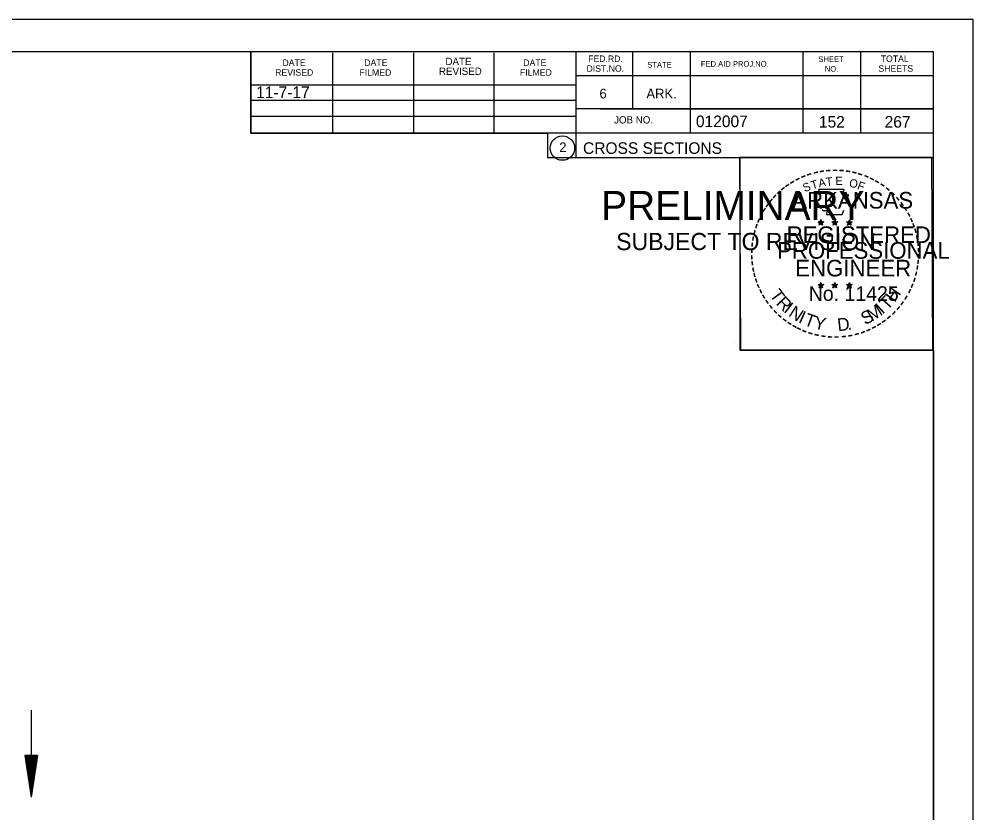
# Model space of a CAD drawing. Extents: x 1374311 to 1383814, y 384102 to 406278.
# Drawn here: x 1381676.6 to 1381791.6, y 385082.2 to 385178 of the extents above; entities that cross this region are included whole.
import ezdxf

# ---------------------------------------------------------------- set-up
doc = ezdxf.new("R2010")
doc.units = 0
for name, color, linetype in [('R_Border', 7, 'Continuous'), ('R_Border PE', 7, 'Continuous'), ('R_Border Prem', 7, 'Continuous'), ('R_Draft', 7, 'Continuous'), ('R_Fin Surface', 7, 'Continuous'), ('R_No Plot', 7, 'Continuous'), ('R_Water', 7, 'Continuous')]:
    doc.layers.add(name, color=color, linetype=linetype)

msp = doc.modelspace()

# ---------------------------------------------------------------- linework, layer by layer
at = {"layer": 'R_Border'}
for p, q in [((1381470.66, 385174.06), (1381786.84, 385174.06)), ((1381704.58, 385164.18), (1381704.58, 385174.06)), ((1381714.44, 385164.18), (1381714.44, 385173.86)), ((1381724.2, 385164.18), (1381724.2, 385173.86)), ((1381733.88, 385164.18), (1381733.88, 385173.86)), ((1381743.74, 385174.06), (1381743.74, 385161.26)), ((1381750.58, 385174.06), (1381750.58, 385167.12)), ((1381757.52, 385174.06), (1381757.52, 385164.18)), ((1381771.1, 385174.06), (1381771.1, 385164.18)), ((1381778.04, 385174.06), (1381778.04, 385164.18)), ((1381786.84, 384968.6), (1381786.84, 385174.06)), ((1381786.84, 385171.12), (1381743.74, 385171.12)), ((1381786.84, 385171.14), (1381786.84, 385171.14)), ((1381704.58, 385170.04), (1381743.74, 385170.04)), ((1381704.58, 385168.18), (1381743.74, 385168.18)), ((1381786.84, 385167.12), (1381743.74, 385167.12)), ((1381746.7, 385167.12), (1381786.84, 385167.12)), ((1381704.58, 385164.18), (1381704.58, 385166.24)), ((1381704.58, 385166.24), (1381743.74, 385166.24)), ((1381786.84, 385164.18), (1381704.58, 385164.18)), ((1381743.74, 385161.26), (1381786.84, 385161.26))]:
    msp.add_line(p, q, dxfattribs=at)
msp.add_circle((1381742.12, 385162.39), 1.47, dxfattribs=at)
at = {"layer": 'R_Border PE'}
for p, q in [((1381772.92, 385153.51), (1381773.27, 385153.4)), ((1381772.92, 385153.51), (1381773.18, 385153.47)), ((1381772.92, 385153.51), (1381773.16, 385153.39)), ((1381773.06, 385153.1), (1381773.27, 385153.4)), ((1381773.06, 385153.1), (1381773.18, 385153.35)), ((1381773.06, 385153.1), (1381773.27, 385153.32)), ((1381773.27, 385153.77), (1381773.23, 385153.51)), ((1381773.27, 385153.4), (1381773.27, 385153.77)), ((1381773.27, 385153.77), (1381773.32, 385153.52)), ((1381773.62, 385153.51), (1381773.27, 385153.4)), ((1381773.48, 385153.1), (1381773.27, 385153.4)), ((1381773.48, 385153.1), (1381773.27, 385153.32)), ((1381773.62, 385153.51), (1381773.33, 385153.46)), ((1381773.48, 385153.1), (1381773.35, 385153.39)), ((1381773.62, 385153.51), (1381773.41, 385153.41)), ((1381774.59, 385153.51), (1381774.94, 385153.4)), ((1381774.59, 385153.51), (1381774.85, 385153.47)), ((1381774.59, 385153.51), (1381774.83, 385153.39)), ((1381774.73, 385153.1), (1381774.94, 385153.4)), ((1381774.73, 385153.1), (1381774.85, 385153.35)), ((1381774.73, 385153.1), (1381774.94, 385153.32)), ((1381774.94, 385153.77), (1381774.9, 385153.51)), ((1381774.94, 385153.4), (1381774.94, 385153.77)), ((1381774.94, 385153.77), (1381774.99, 385153.52)), ((1381775.29, 385153.51), (1381774.94, 385153.4)), ((1381775.15, 385153.1), (1381774.94, 385153.4)), ((1381775.15, 385153.1), (1381774.94, 385153.32)), ((1381775.29, 385153.51), (1381775, 385153.46)), ((1381775.15, 385153.1), (1381775.02, 385153.39)), ((1381775.29, 385153.51), (1381775.08, 385153.41)), ((1381776.36, 385153.5), (1381776.71, 385153.39)), ((1381776.36, 385153.5), (1381776.61, 385153.45)), ((1381776.36, 385153.5), (1381776.59, 385153.38)), ((1381776.49, 385153.09), (1381776.71, 385153.39)), ((1381776.49, 385153.09), (1381776.62, 385153.34)), ((1381776.49, 385153.09), (1381776.7, 385153.31)), ((1381776.71, 385153.75), (1381776.66, 385153.5)), ((1381776.92, 385153.09), (1381776.7, 385153.31)), ((1381776.71, 385153.39), (1381776.71, 385153.75)), ((1381776.71, 385153.75), (1381776.75, 385153.5)), ((1381777.05, 385153.5), (1381776.71, 385153.39)), ((1381776.92, 385153.09), (1381776.71, 385153.39)), ((1381777.05, 385153.5), (1381776.77, 385153.45)), ((1381776.92, 385153.09), (1381776.78, 385153.38)), ((1381777.05, 385153.5), (1381776.85, 385153.4)), ((1381773.27, 385146.19), (1381773.23, 385145.94)), ((1381773.27, 385145.83), (1381773.27, 385146.19)), ((1381773.27, 385146.19), (1381773.32, 385145.94)), ((1381774.94, 385146.19), (1381774.9, 385145.94)), ((1381774.94, 385145.83), (1381774.94, 385146.19)), ((1381774.94, 385146.19), (1381774.99, 385145.94)), ((1381776.7, 385146.18), (1381776.66, 385145.93)), ((1381776.7, 385145.82), (1381776.7, 385146.18)), ((1381776.7, 385146.18), (1381776.75, 385145.93)), ((1381772.92, 385145.94), (1381773.27, 385145.83)), ((1381772.92, 385145.94), (1381773.17, 385145.89)), ((1381772.92, 385145.94), (1381773.16, 385145.82)), ((1381773.05, 385145.53), (1381773.27, 385145.83)), ((1381773.05, 385145.53), (1381773.18, 385145.77)), ((1381773.05, 385145.53), (1381773.27, 385145.75)), ((1381773.61, 385145.94), (1381773.27, 385145.83)), ((1381773.48, 385145.53), (1381773.27, 385145.83)), ((1381773.48, 385145.53), (1381773.27, 385145.74)), ((1381773.61, 385145.94), (1381773.33, 385145.89)), ((1381773.48, 385145.53), (1381773.34, 385145.82)), ((1381773.61, 385145.94), (1381773.41, 385145.84)), ((1381774.59, 385145.94), (1381774.94, 385145.83)), ((1381774.59, 385145.94), (1381774.84, 385145.89)), ((1381774.59, 385145.94), (1381774.82, 385145.82)), ((1381774.72, 385145.53), (1381774.94, 385145.83)), ((1381774.72, 385145.53), (1381774.85, 385145.77)), ((1381774.72, 385145.53), (1381774.93, 385145.75)), ((1381775.15, 385145.53), (1381774.93, 385145.74)), ((1381775.28, 385145.94), (1381774.94, 385145.83)), ((1381775.15, 385145.53), (1381774.94, 385145.83)), ((1381775.28, 385145.94), (1381775, 385145.89)), ((1381775.15, 385145.53), (1381775.01, 385145.82)), ((1381775.28, 385145.94), (1381775.08, 385145.84)), ((1381776.35, 385145.93), (1381776.7, 385145.82)), ((1381776.35, 385145.93), (1381776.61, 385145.88)), ((1381776.35, 385145.93), (1381776.59, 385145.81)), ((1381776.49, 385145.52), (1381776.7, 385145.82)), ((1381776.49, 385145.52), (1381776.61, 385145.76)), ((1381776.49, 385145.52), (1381776.7, 385145.74)), ((1381777.05, 385145.93), (1381776.7, 385145.82)), ((1381776.92, 385145.52), (1381776.7, 385145.82)), ((1381776.92, 385145.52), (1381776.7, 385145.73)), ((1381777.05, 385145.93), (1381776.76, 385145.88)), ((1381776.92, 385145.52), (1381776.78, 385145.81)), ((1381777.05, 385145.93), (1381776.85, 385145.83))]:
    msp.add_line(p, q, dxfattribs=at)
for points in [[(1381772.96, 385157.39), (1381773.23, 385156.56)], [(1381776.47, 385156.47), (1381776.62, 385156.75), (1381775.93, 385156.73), (1381776.08, 385157.39), (1381772.96, 385157.39)], [(1381773.46, 385154.97), (1381773.46, 385154.88), (1381774.02, 385154.86), (1381773.96, 385154.39), (1381775.83, 385154.39), (1381776.04, 385154.92)], [(1381773.27, 385153.77), (1381773.48, 385153.1), (1381772.92, 385153.51), (1381773.62, 385153.51), (1381773.06, 385153.1), (1381773.27, 385153.77)], [(1381774.94, 385153.77), (1381775.15, 385153.1), (1381774.59, 385153.51), (1381775.29, 385153.51), (1381774.73, 385153.1), (1381774.94, 385153.77)], [(1381776.71, 385153.75), (1381776.92, 385153.09), (1381776.36, 385153.5), (1381777.05, 385153.5), (1381776.49, 385153.09), (1381776.71, 385153.75)], [(1381773.27, 385146.19), (1381773.48, 385145.53), (1381772.92, 385145.94), (1381773.61, 385145.94), (1381773.05, 385145.53), (1381773.27, 385146.19)], [(1381774.94, 385146.19), (1381775.15, 385145.53), (1381774.59, 385145.94), (1381775.28, 385145.94), (1381774.72, 385145.53), (1381774.94, 385146.19)], [(1381776.7, 385146.18), (1381776.92, 385145.52), (1381776.35, 385145.93), (1381777.05, 385145.93), (1381776.49, 385145.52), (1381776.7, 385146.18)]]:
    msp.add_lwpolyline(points, dxfattribs=at)
for centre, radius in [((1381773.27, 385153.4), 0.172), ((1381773.27, 385153.4), 0.145), ((1381773.27, 385153.4), 0.116), ((1381773.27, 385153.4), 0.0991), ((1381773.27, 385153.4), 0.0747), ((1381773.27, 385153.4), 0.0495), ((1381773.27, 385153.4), 0.0296), ((1381774.94, 385153.4), 0.172), ((1381774.94, 385153.4), 0.145), ((1381774.94, 385153.4), 0.116), ((1381774.94, 385153.4), 0.0991), ((1381774.94, 385153.4), 0.0747), ((1381774.94, 385153.4), 0.0495), ((1381774.94, 385153.4), 0.0296), ((1381776.7, 385153.39), 0.172), ((1381776.7, 385153.39), 0.145), ((1381776.7, 385153.39), 0.116), ((1381776.7, 385153.39), 0.0991), ((1381776.7, 385153.39), 0.0747), ((1381776.7, 385153.39), 0.0495), ((1381776.7, 385153.39), 0.0296), ((1381773.27, 385145.83), 0.172), ((1381773.27, 385145.83), 0.145), ((1381773.27, 385145.83), 0.116), ((1381773.27, 385145.83), 0.0991), ((1381773.27, 385145.83), 0.0747), ((1381773.27, 385145.83), 0.0495), ((1381773.27, 385145.83), 0.0296), ((1381774.94, 385145.83), 0.172), ((1381774.94, 385145.83), 0.145), ((1381774.94, 385145.83), 0.116), ((1381774.94, 385145.83), 0.0991), ((1381774.94, 385145.83), 0.0747), ((1381774.94, 385145.83), 0.0495), ((1381774.94, 385145.83), 0.0296), ((1381776.7, 385145.82), 0.172), ((1381776.7, 385145.82), 0.145), ((1381776.7, 385145.82), 0.116), ((1381776.7, 385145.82), 0.0991), ((1381776.7, 385145.82), 0.0747), ((1381776.7, 385145.82), 0.0495), ((1381776.7, 385145.82), 0.0296)]:
    msp.add_circle(centre, radius, dxfattribs=at)
at = {"layer": 'R_Draft'}
for p, q in [((1381677.34, 385089.13), (1381678.09, 385084.13)), ((1381678.84, 385089.13), (1381677.34, 385089.13)), ((1381677.47, 385089.13), (1381678.09, 385084.96)), ((1381677.6, 385089.13), (1381678.09, 385085.82)), ((1381677.72, 385089.13), (1381678.09, 385086.65)), ((1381677.85, 385089.13), (1381678.09, 385087.5)), ((1381677.98, 385089.13), (1381678.09, 385088.34)), ((1381678.84, 385089.13), (1381678.09, 385084.13)), ((1381678.34, 385089.13), (1381678.09, 385087.5)), ((1381678.59, 385089.13), (1381678.09, 385085.82)), ((1381678.72, 385089.13), (1381678.09, 385084.96)), ((1381678.47, 385089.13), (1381678.09, 385086.65)), ((1381678.21, 385089.13), (1381678.09, 385088.34))]:
    msp.add_line(p, q, dxfattribs=at)
at = {"layer": 'R_No Plot'}
for p, q in [((1381458.26, 385177.95), (1381791.59, 385177.95)), ((1381762.87, 385138.8), (1381762.87, 385138.8))]:
    msp.add_line(p, q, dxfattribs=at)
for points in [[(1381458.25, 385177.95), (1381791.59, 385177.95), (1381791.59, 384964.61), (1381458.25, 384964.61)], [(1381704.58, 385174.06), (1381704.58, 385164.18), (1381740.31, 385164.18), (1381740.31, 385161.26), (1381763.51, 385161.26), (1381763.51, 385138.04), (1381786.84, 385138.04), (1381786.84, 384968.6), (1381470.66, 384968.6), (1381470.66, 385174.06)], [(1381763.51, 385161.29), (1381786.61, 385161.29), (1381786.72, 385138.04), (1381763.62, 385138.04)]]:
    msp.add_lwpolyline(points, close=True, dxfattribs=at)
at = {"layer": 'R_Water'}
msp.add_line((1381678.09, 385094.63), (1381678.09, 385084.13), dxfattribs=at)

# ---------------------------------------------------------------- texts
at = {"layer": 'R_Border'}
for s, height, p in [('DATE', 0.782, (1381708.38, 385172.3)), ('DATE', 0.782, (1381718.24, 385172.3)), ('DATE', 0.879, (1381728.02, 385172.4)), ('DATE', 0.782, (1381737.4, 385172.3)), ('FED.RD.', 0.782, (1381745.22, 385172.78)), ('STATE', 0.684, (1381752.34, 385172.1)), ('FED.AID PROJ.NO.', 0.684, (1381758.8, 385172.2)), ('SHEET', 0.684, (1381772.96, 385172.78)), ('TOTAL', 0.782, (1381780.48, 385172.78)), ('REVISED', 0.782, (1381707.5, 385171.12)), ('FILMED', 0.782, (1381717.66, 385171.12)), ('REVISED', 0.879, (1381727.24, 385171.22)), ('FILMED', 0.782, (1381737, 385171.12)), ('DIST.NO.', 0.782, (1381745.02, 385171.6)), ('NO.', 0.684, (1381773.74, 385171.6)), ('SHEETS', 0.782, (1381780.2, 385171.6)), ('6', 1.17, (1381746.58, 385168.38)), ('ARK.', 1.172, (1381752.24, 385168.38)), ('JOB NO.', 0.879, (1381748.34, 385165.36)), ('012007', 1.4, (1381758.21, 385164.92)), ('2', 1.17, (1381741.74, 385161.91)), ('CROSS SECTIONS', 1.4, (1381744.6, 385161.69))]:
    msp.add_text(s, height=height, rotation=360, dxfattribs=at).set_placement(p)
at = {"layer": 'R_Border PE'}
for s, height, rotation, p in [('-', 1.6, 28.7918, (1381770.44, 385157.93)), ('-', 1.6, 24.3072, (1381771.08, 385158.25)), ('-', 1.6, 19.1761, (1381771.71, 385158.52)), ('-', 1.6, 13.6301, (1381772.46, 385158.76)), ('-', 1.6, 10.2193, (1381773.14, 385158.92)), ('T', 1, 6.0228, (1381773.91, 385157.82)), ('-', 1.6, 5.8968, (1381773.87, 385159.03)), ('-', 1.6, 0.1862, (1381774.64, 385159.1)), ('E', 1, 0.8323, (1381775.01, 385157.93)), ('-', 1.6, 357.743, (1381775.36, 385159.09)), ('-', 1.6, 352.1617, (1381776.11, 385159.03)), ('-', 1.6, 347.2049, (1381776.83, 385158.92)), ('-', 1.6, 342.3362, (1381777.46, 385158.76)), ('-', 1.6, 337.8551, (1381778.2, 385158.54)), ('-', 1.6, 334.1211, (1381778.83, 385158.27)), ('-', 1.6, 38.9507, (1381768.79, 385156.79)), ('-', 1.6, 36.2317, (1381769.27, 385157.17)), ('-', 1.6, 34.0636, (1381769.85, 385157.56)), ('S', 1, 21.594, (1381771.32, 385157.07)), ('T', 1, 16.4036, (1381772.23, 385157.4)), ('A', 1, 11.2132, (1381773.06, 385157.65)), ('O', 1, 350.4515, (1381776.62, 385157.72)), ('F', 1, 340.0707, (1381777.57, 385157.49)), ('-', 1.6, 329.6409, (1381779.41, 385157.99)), ('-', 1.6, 325.8627, (1381780.05, 385157.63)), ('-', 1.6, 320.5297, (1381780.66, 385157.2)), ('-', 1.6, 48.423, (1381767.91, 385155.89)), ('-', 1.6, 42.9622, (1381768.36, 385156.37)), ('ARKANSAS', 2, 360, (1381769.82, 385155.1)), ('-', 1.6, 315.5786, (1381781.26, 385156.71)), ('-', 1.6, 309.8797, (1381781.83, 385156.16)), ('-', 1.6, 54.2325, (1381767.1, 385154.84)), ('-', 1.6, 50.6142, (1381767.51, 385155.41)), ('-', 1.6, 306.6522, (1381782.35, 385155.56)), ('-', 1.6, 62.8713, (1381766.46, 385153.7)), ('-', 1.6, 58.0706, (1381766.77, 385154.31)), ('-', 1.4, 303.6753, (1381782.84, 385154.99)), ('-', 1.6, 299.6684, (1381783.16, 385154.38)), ('-', 1.6, 72.3945, (1381765.98, 385152.46)), ('-', 1.6, 67.7743, (1381766.2, 385153.09)), ('DWB', 0.01, 360, (1381773.26, 385153.4)), ('DWB', 0.01, 360, (1381774.93, 385153.4)), ('DWB', 0.01, 360, (1381776.69, 385153.38)), ('-', 1.6, 294.6628, (1381783.48, 385153.77)), ('-', 1.6, 290.5728, (1381783.74, 385153.2)), ('-', 1.6, 75.461, (1381765.78, 385151.74)), ('REGISTERED', 2, 360, (1381769.14, 385150.95)), ('-', 1.6, 285.1233, (1381783.97, 385152.62)), ('-', 1.6, 280.5493, (1381784.17, 385151.87)), ('-', 1.6, 85.1863, (1381765.57, 385150.34)), ('-', 1.6, 81.2013, (1381765.65, 385151.03)), ('PROFESSIONAL', 2, 360, (1381767.99, 385149.05)), ('-', 1.6, 276.5962, (1381784.33, 385151.11)), ('-', 1.6, 89.0622, (1381765.55, 385149.64)), ('-', 1.6, 274.3301, (1381784.39, 385150.38)), ('-', 1.6, 269.9407, (1381784.43, 385149.75)), ('-', 1.6, 94.1959, (1381765.58, 385148.91)), ('-', 1.6, 98.9479, (1381765.66, 385148.25)), ('ENGINEER', 2, 360, (1381770.18, 385146.92)), ('-', 1.6, 263.5172, (1381784.41, 385149.09)), ('-', 1.6, 101.7149, (1381765.79, 385147.51)), ('-', 1.6, 105.4578, (1381765.95, 385146.92)), ('-', 1.6, 255.7626, (1381784.23, 385147.75)), ('-', 1.6, 260.9953, (1381784.34, 385148.43)), ('-', 1.6, 109.0874, (1381766.17, 385146.29)), ('-', 1.6, 252.8681, (1381784.05, 385147.03)), ('-', 1.6, 114.0643, (1381766.42, 385145.69)), ('-', 1.6, 115.7289, (1381766.73, 385145.07)), ('T', 1.54, 306.0406, (1381767.03, 385144.67)), ('No. 11425', 1.757, 360, (1381771.8, 385143.97)), ('DWB', 0.01, 360, (1381773.25, 385145.82)), ('DWB', 0.01, 360, (1381774.92, 385145.82)), ('DWB', 0.01, 360, (1381776.69, 385145.81)), ('H', 1.54, 54.6088, (1381782.15, 385143.7)), ('-', 1.6, 244.6197, (1381783.56, 385145.73)), ('-', 1.6, 247.8887, (1381783.82, 385146.36)), ('-', 1.6, 120.4471, (1381767.08, 385144.49)), ('-', 1.6, 125.8934, (1381767.49, 385143.93)), ('R', 1.54, 314.005, (1381767.79, 385143.62)), ('T', 1.54, 46.6444, (1381781.26, 385142.76)), ('-', 1.6, 233.8452, (1381782.77, 385144.33)), ('-', 1.6, 239.0712, (1381783.17, 385144.98)), ('-', 1.6, 130.7181, (1381767.95, 385143.37)), ('-', 1.6, 134.2238, (1381768.47, 385142.83)), ('I', 1.54, 321.9694, (1381768.69, 385142.69)), ('N', 1.54, 326.5002, (1381769.26, 385142.21)), ('I', 1.54, 335.3603, (1381770.47, 385141.43)), ('S', 1.54, 26.9312, (1381778.57, 385141.03)), ('M', 1.54, 32.6563, (1381779.41, 385141.43)), ('I', 1.54, 42.1136, (1381780.7, 385142.28)), ('-', 1.6, 225.7653, (1381781.86, 385143.2)), ('-', 1.6, 231.2538, (1381782.34, 385143.76)), ('-', 1.6, 138.9338, (1381768.99, 385142.37)), ('-', 1.6, 144.6463, (1381769.55, 385141.96)), ('T', 1.54, 339.8912, (1381771.13, 385141.1)), ('Y', 1.54, 347.8556, (1381772.34, 385140.66)), ('D', 1.54, 6.3969, (1381775.33, 385140.3)), ('-', 1.6, 215.7363, (1381780.79, 385142.22)), ('-', 1.6, 221.0851, (1381781.33, 385142.69)), ('-', 1.6, 148.0898, (1381770.11, 385141.59)), ('-', 1.6, 151.5704, (1381770.69, 385141.26)), ('-', 1.6, 154.6002, (1381771.21, 385141.02)), ('-', 1.6, 158.5612, (1381771.83, 385140.76)), ('.', 1.54, 13.7642, (1381776.52, 385140.42)), ('-', 1.6, 200.7184, (1381778.45, 385140.89)), ('-', 1.6, 204.2516, (1381779.07, 385141.16)), ('-', 1.6, 207.3568, (1381779.69, 385141.48)), ('-', 1.6, 212.2491, (1381780.25, 385141.83)), ('-', 1.6, 162.7983, (1381772.52, 385140.55)), ('-', 1.6, 167.5555, (1381773.24, 385140.39)), ('-', 1.6, 173.1155, (1381774.01, 385140.28)), ('-', 1.6, 176.5183, (1381774.76, 385140.22)), ('-', 1.6, 181.5918, (1381775.5, 385140.24)), ('-', 1.6, 185.8167, (1381776.31, 385140.32)), ('-', 1.6, 191.2858, (1381777.04, 385140.45)), ('-', 1.6, 195.4743, (1381777.77, 385140.65))]:
    msp.add_text(s, height=height, rotation=rotation, dxfattribs=at).set_placement(p)
at = {"layer": 'R_Border Prem'}
for s, height, p in [('PRELIMINARY', 3.5, (1381746.79, 385153.72)), ('DWB', 0.01, (1381747.53, 385155.57)), ('SUBJECT TO REVISION', 2.0751, (1381748.6, 385150.09))]:
    msp.add_text(s, height=height, rotation=360, dxfattribs=at).set_placement(p)
at = {"layer": 'R_Fin Surface'}
msp.add_text('11-7-17', height=1.4, dxfattribs=at).set_placement((1381705.2, 385168.42))
at = {"layer": 'R_Water'}
for s, p in [('152', (1381773.03, 385164.86)), ('267', (1381780.95, 385164.86))]:
    msp.add_text(s, height=1.4, rotation=360, dxfattribs=at).set_placement(p)

doc.saveas('drawing.dxf')
